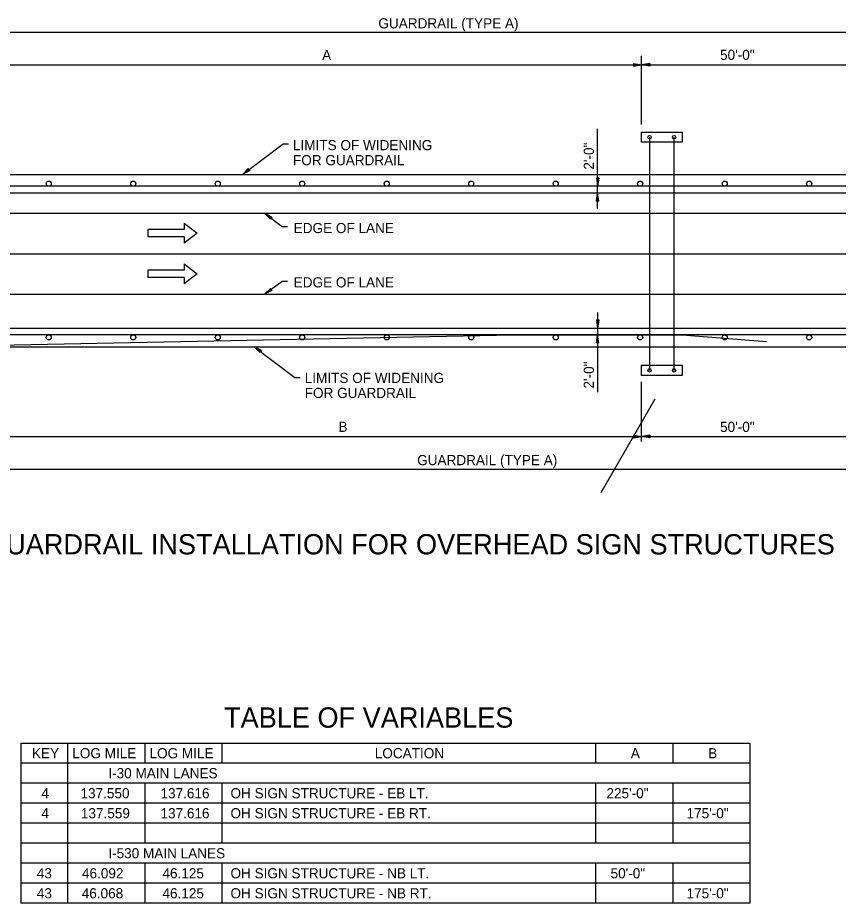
# Model space of a CAD drawing. Extents: x 1373853 to 1374003, y 380191 to 380927.
# Drawn here: x 1373903.9 to 1373952.4, y 380851.9 to 380904.4 of the extents above; entities that cross this region are included whole.
import ezdxf

# ---------------------------------------------------------------- set-up
doc = ezdxf.new("R2010")
doc.units = 0
for name, color, linetype in [('2', 7, 'Continuous'), ('44', 7, 'Continuous'), ('7', 7, 'Continuous'), ('8', 7, 'Continuous'), ('Default', 7, 'Continuous'), ('E_Existing ROW', 7, 'Continuous'), ('Plan Notes', 7, 'Continuous'), ('R_Proposed Road', 7, 'Continuous'), ('R_SIGN_OH', 7, 'Continuous')]:
    doc.layers.add(name, color=color, linetype=linetype)

msp = doc.modelspace()

# ---------------------------------------------------------------- linework, layer by layer
at = {"layer": '2'}
for p, q in [((1373888.075, 380903.499), (1373962.85, 380903.499)), ((1373940.776, 380898.049), (1373940.776, 380902.098)), ((1373903.184, 380901.577), (1373965.149, 380901.575)), ((1373940.776, 380898.049), (1373940.776, 380898.903)), ((1373938.173, 380893.067), (1373938.173, 380897.788)), ((1373917.158, 380895.091), (1373919.557, 380896.904)), ((1373919.557, 380896.904), (1373919.876, 380896.904)), ((1373918.466, 380892.791), (1373919.498, 380892.01)), ((1373919.498, 380892.01), (1373919.818, 380892.01)), ((1373918.466, 380887.991), (1373919.498, 380888.771)), ((1373919.498, 380888.771), (1373919.818, 380888.771)), ((1373938.173, 380886.914), (1373938.173, 380882.193)), ((1373917.854, 380884.891), (1373920.253, 380883.077)), ((1373920.253, 380883.077), (1373920.572, 380883.077)), ((1373940.776, 380879.283), (1373940.776, 380882.812)), ((1373903.176, 380879.572), (1373967.577, 380879.572)), ((1373888.057, 380877.648), (1373962.85, 380877.648))]:
    msp.add_line(p, q, dxfattribs=at)
at = {"layer": '44'}
for p, q in [((1373877.32, 380893.991), (1373970.938, 380893.991)), ((1373877.32, 380885.991), (1373970.938, 380885.991))]:
    msp.add_line(p, q, dxfattribs=at)
at = {"layer": '7'}
for p, q in [((1373940.296, 380901.649), (1373940.776, 380901.575)), ((1373940.296, 380901.649), (1373940.296, 380901.503)), ((1373940.296, 380901.634), (1373940.694, 380901.575)), ((1373940.296, 380901.622), (1373940.613, 380901.575)), ((1373940.296, 380901.61), (1373940.532, 380901.575)), ((1373940.296, 380901.599), (1373940.453, 380901.575)), ((1373940.296, 380901.587), (1373940.372, 380901.575)), ((1373940.296, 380901.503), (1373940.776, 380901.575)), ((1373940.296, 380901.553), (1373940.453, 380901.575)), ((1373940.296, 380901.529), (1373940.613, 380901.575)), ((1373940.296, 380901.515), (1373940.694, 380901.575)), ((1373940.296, 380901.539), (1373940.532, 380901.575)), ((1373940.296, 380901.565), (1373940.372, 380901.575)), ((1373941.256, 380901.649), (1373940.776, 380901.575)), ((1373941.256, 380901.503), (1373940.776, 380901.575)), ((1373941.256, 380901.634), (1373940.857, 380901.575)), ((1373941.256, 380901.515), (1373940.857, 380901.575)), ((1373941.256, 380901.622), (1373940.938, 380901.575)), ((1373941.256, 380901.529), (1373940.938, 380901.575)), ((1373941.256, 380901.61), (1373941.019, 380901.575)), ((1373941.256, 380901.539), (1373941.019, 380901.575)), ((1373941.256, 380901.599), (1373941.098, 380901.575)), ((1373941.256, 380901.553), (1373941.098, 380901.575)), ((1373941.256, 380901.587), (1373941.179, 380901.575)), ((1373941.256, 380901.565), (1373941.179, 380901.575)), ((1373941.256, 380901.649), (1373941.256, 380901.503)), ((1373917.498, 380895.435), (1373917.158, 380895.091)), ((1373917.585, 380895.322), (1373917.158, 380895.091)), ((1373917.507, 380895.427), (1373917.223, 380895.137)), ((1373917.578, 380895.33), (1373917.223, 380895.137)), ((1373917.516, 380895.415), (1373917.29, 380895.188)), ((1373917.569, 380895.34), (1373917.29, 380895.188)), ((1373917.521, 380895.405), (1373917.353, 380895.235)), ((1373917.563, 380895.35), (1373917.353, 380895.235)), ((1373917.527, 380895.397), (1373917.416, 380895.284)), ((1373917.554, 380895.36), (1373917.416, 380895.284)), ((1373917.534, 380895.387), (1373917.483, 380895.333)), ((1373917.55, 380895.372), (1373917.483, 380895.333)), ((1373917.585, 380895.322), (1373917.498, 380895.435)), ((1373938.102, 380894.871), (1373938.173, 380894.391)), ((1373938.245, 380894.871), (1373938.102, 380894.871)), ((1373938.114, 380894.871), (1373938.173, 380894.472)), ((1373938.126, 380894.871), (1373938.173, 380894.553)), ((1373938.138, 380894.871), (1373938.173, 380894.634)), ((1373938.15, 380894.871), (1373938.173, 380894.715)), ((1373938.161, 380894.871), (1373938.173, 380894.794)), ((1373938.245, 380894.871), (1373938.173, 380894.391)), ((1373938.197, 380894.871), (1373938.173, 380894.715)), ((1373938.221, 380894.871), (1373938.173, 380894.553)), ((1373938.233, 380894.871), (1373938.173, 380894.472)), ((1373938.209, 380894.871), (1373938.173, 380894.634)), ((1373938.185, 380894.871), (1373938.173, 380894.794)), ((1373938.099, 380893.511), (1373938.173, 380893.991)), ((1373938.245, 380893.511), (1373938.173, 380893.991)), ((1373938.099, 380893.511), (1373938.245, 380893.511)), ((1373938.114, 380893.511), (1373938.173, 380893.909)), ((1373938.126, 380893.511), (1373938.173, 380893.828)), ((1373938.138, 380893.511), (1373938.173, 380893.747)), ((1373938.15, 380893.511), (1373938.173, 380893.668)), ((1373938.161, 380893.511), (1373938.173, 380893.587)), ((1373938.233, 380893.511), (1373938.173, 380893.909)), ((1373938.219, 380893.511), (1373938.173, 380893.828)), ((1373938.209, 380893.511), (1373938.173, 380893.747)), ((1373938.195, 380893.511), (1373938.173, 380893.668)), ((1373938.183, 380893.511), (1373938.173, 380893.587)), ((1373918.893, 380892.559), (1373918.466, 380892.791)), ((1373918.806, 380892.446), (1373918.466, 380892.791)), ((1373918.886, 380892.552), (1373918.531, 380892.744)), ((1373918.815, 380892.454), (1373918.531, 380892.744)), ((1373918.824, 380892.467), (1373918.598, 380892.693)), ((1373918.877, 380892.541), (1373918.598, 380892.693)), ((1373918.871, 380892.532), (1373918.661, 380892.646)), ((1373918.828, 380892.476), (1373918.661, 380892.646)), ((1373918.835, 380892.484), (1373918.723, 380892.597)), ((1373918.862, 380892.521), (1373918.723, 380892.597)), ((1373918.842, 380892.494), (1373918.791, 380892.548)), ((1373918.858, 380892.509), (1373918.791, 380892.548)), ((1373918.893, 380892.559), (1373918.806, 380892.446)), ((1373918.806, 380888.335), (1373918.466, 380887.991)), ((1373918.893, 380888.222), (1373918.466, 380887.991)), ((1373918.815, 380888.327), (1373918.531, 380888.037)), ((1373918.886, 380888.23), (1373918.531, 380888.037)), ((1373918.824, 380888.315), (1373918.598, 380888.088)), ((1373918.877, 380888.24), (1373918.598, 380888.088)), ((1373918.828, 380888.305), (1373918.661, 380888.135)), ((1373918.871, 380888.25), (1373918.661, 380888.135)), ((1373918.835, 380888.297), (1373918.723, 380888.184)), ((1373918.862, 380888.26), (1373918.723, 380888.184)), ((1373918.842, 380888.287), (1373918.791, 380888.233)), ((1373918.858, 380888.272), (1373918.791, 380888.233)), ((1373918.893, 380888.222), (1373918.806, 380888.335)), ((1373938.099, 380886.471), (1373938.173, 380885.991)), ((1373938.099, 380886.471), (1373938.245, 380886.471)), ((1373938.114, 380886.471), (1373938.173, 380886.072)), ((1373938.126, 380886.471), (1373938.173, 380886.153)), ((1373938.138, 380886.471), (1373938.173, 380886.234)), ((1373938.15, 380886.471), (1373938.173, 380886.313)), ((1373938.161, 380886.471), (1373938.173, 380886.394)), ((1373938.245, 380886.471), (1373938.173, 380885.991)), ((1373938.195, 380886.471), (1373938.173, 380886.313)), ((1373938.219, 380886.471), (1373938.173, 380886.153)), ((1373938.233, 380886.471), (1373938.173, 380886.072)), ((1373938.209, 380886.471), (1373938.173, 380886.234)), ((1373938.183, 380886.471), (1373938.173, 380886.394)), ((1373938.102, 380885.111), (1373938.173, 380885.591)), ((1373938.245, 380885.111), (1373938.173, 380885.591)), ((1373938.245, 380885.111), (1373938.102, 380885.111)), ((1373938.114, 380885.111), (1373938.173, 380885.509)), ((1373938.126, 380885.111), (1373938.173, 380885.428)), ((1373938.138, 380885.111), (1373938.173, 380885.347)), ((1373938.15, 380885.111), (1373938.173, 380885.266)), ((1373938.161, 380885.111), (1373938.173, 380885.187)), ((1373938.233, 380885.111), (1373938.173, 380885.509)), ((1373938.221, 380885.111), (1373938.173, 380885.428)), ((1373938.209, 380885.111), (1373938.173, 380885.347)), ((1373938.197, 380885.111), (1373938.173, 380885.266)), ((1373938.185, 380885.111), (1373938.173, 380885.187)), ((1373918.281, 380884.659), (1373917.854, 380884.891)), ((1373918.194, 380884.547), (1373917.854, 380884.891)), ((1373918.274, 380884.652), (1373917.919, 380884.844)), ((1373918.203, 380884.554), (1373917.919, 380884.844)), ((1373918.212, 380884.567), (1373917.986, 380884.793)), ((1373918.265, 380884.641), (1373917.986, 380884.793)), ((1373918.259, 380884.632), (1373918.049, 380884.746)), ((1373918.216, 380884.576), (1373918.049, 380884.746)), ((1373918.223, 380884.584), (1373918.111, 380884.697)), ((1373918.25, 380884.621), (1373918.111, 380884.697)), ((1373918.23, 380884.594), (1373918.179, 380884.648)), ((1373918.246, 380884.609), (1373918.179, 380884.648)), ((1373918.281, 380884.659), (1373918.194, 380884.547)), ((1373940.296, 380879.646), (1373940.776, 380879.572)), ((1373940.296, 380879.646), (1373940.296, 380879.5)), ((1373940.296, 380879.632), (1373940.694, 380879.572)), ((1373940.296, 380879.62), (1373940.613, 380879.572)), ((1373940.296, 380879.608), (1373940.532, 380879.572)), ((1373940.296, 380879.596), (1373940.453, 380879.572)), ((1373940.296, 380879.584), (1373940.372, 380879.572)), ((1373940.296, 380879.5), (1373940.776, 380879.572)), ((1373940.296, 380879.551), (1373940.453, 380879.572)), ((1373940.296, 380879.527), (1373940.613, 380879.572)), ((1373940.296, 380879.512), (1373940.694, 380879.572)), ((1373940.296, 380879.536), (1373940.532, 380879.572)), ((1373940.296, 380879.562), (1373940.372, 380879.572)), ((1373941.256, 380879.646), (1373940.776, 380879.572)), ((1373941.256, 380879.5), (1373940.776, 380879.572)), ((1373941.256, 380879.632), (1373940.857, 380879.572)), ((1373941.256, 380879.512), (1373940.857, 380879.572)), ((1373941.256, 380879.62), (1373940.938, 380879.572)), ((1373941.256, 380879.527), (1373940.938, 380879.572)), ((1373941.256, 380879.608), (1373941.019, 380879.572)), ((1373941.256, 380879.536), (1373941.019, 380879.572)), ((1373941.256, 380879.596), (1373941.098, 380879.572)), ((1373941.256, 380879.551), (1373941.098, 380879.572)), ((1373941.256, 380879.584), (1373941.179, 380879.572)), ((1373941.256, 380879.562), (1373941.179, 380879.572)), ((1373941.256, 380879.646), (1373941.256, 380879.5))]:
    msp.add_line(p, q, dxfattribs=at)
at = {"layer": 'Default'}
for p, q in [((1373913.712, 380892.196), (1373913.712, 380891.829)), ((1373913.712, 380892.196), (1373914.475, 380891.608)), ((1373913.712, 380891.829), (1373911.551, 380891.829)), ((1373911.551, 380891.829), (1373911.551, 380891.388)), ((1373913.712, 380891.388), (1373911.551, 380891.388)), ((1373914.475, 380891.608), (1373913.712, 380891.021)), ((1373913.712, 380891.388), (1373913.712, 380891.021)), ((1373913.712, 380889.796), (1373913.712, 380889.429)), ((1373913.712, 380889.796), (1373914.475, 380889.208)), ((1373913.712, 380889.429), (1373911.551, 380889.429)), ((1373911.551, 380889.429), (1373911.551, 380888.988)), ((1373913.712, 380888.988), (1373911.551, 380888.988)), ((1373914.475, 380889.208), (1373913.712, 380888.621)), ((1373913.712, 380888.988), (1373913.712, 380888.621))]:
    msp.add_line(p, q, dxfattribs=at)
at = {"layer": 'E_Existing ROW'}
msp.add_lwpolyline([(1373938.379, 380876.269), (1373941.576, 380881.805)], dxfattribs=at)
msp.add_lwpolyline([(1373938.379, 380876.269), (1373941.576, 380881.805)], dxfattribs=at)
at = {"layer": 'Plan Notes'}
for p, q in [((1373904.047, 380861.425), (1373947.188, 380861.425)), ((1373904.047, 380861.425), (1373904.047, 380851.948)), ((1373906.804, 380861.425), (1373906.804, 380851.948)), ((1373911.374, 380861.425), (1373911.374, 380860.24)), ((1373915.943, 380861.425), (1373915.943, 380860.24)), ((1373938.048, 380861.425), (1373938.048, 380860.24)), ((1373942.618, 380861.425), (1373942.618, 380860.24)), ((1373947.188, 380861.425), (1373947.188, 380851.948)), ((1373911.374, 380859.056), (1373911.374, 380855.502)), ((1373915.943, 380859.056), (1373915.943, 380855.502)), ((1373938.048, 380859.056), (1373938.048, 380855.502)), ((1373942.618, 380859.056), (1373942.618, 380855.502)), ((1373911.374, 380854.317), (1373911.374, 380851.948)), ((1373915.943, 380854.317), (1373915.943, 380851.948)), ((1373938.048, 380854.317), (1373938.048, 380851.948)), ((1373942.618, 380854.317), (1373942.618, 380851.948))]:
    msp.add_line(p, q, dxfattribs=at)
for points in [[(1373947.188, 380860.24), (1373904.047, 380860.24)], [(1373947.188, 380859.056), (1373904.047, 380859.056)], [(1373947.188, 380857.871), (1373904.047, 380857.871)], [(1373947.188, 380856.687), (1373904.047, 380856.687)], [(1373947.188, 380855.502), (1373904.047, 380855.502)], [(1373947.188, 380854.317), (1373904.047, 380854.317)], [(1373947.188, 380853.133), (1373904.047, 380853.133)], [(1373947.188, 380851.948), (1373904.047, 380851.948)]]:
    msp.add_lwpolyline(points, dxfattribs=at)
at = {"layer": 'R_Proposed Road'}
for p, q in [((1373877.32, 380892.791), (1373970.938, 380892.791)), ((1373877.32, 380890.391), (1373970.938, 380890.391)), ((1373877.32, 380887.991), (1373970.938, 380887.991)), ((1373893.176, 380884.791), (1373933.176, 380885.591)), ((1373933.176, 380885.591), (1373943.176, 380885.591)), ((1373943.176, 380885.591), (1373948.176, 380885.191))]:
    msp.add_line(p, q, dxfattribs=at)
for points in [[(1373903.196, 380895.091), (1373933.183, 380895.091)], [(1373933.183, 380895.091), (1373960.176, 380895.091)], [(1373958.176, 380894.791), (1373953.176, 380894.391), (1373940.692, 380894.391)], [(1373905.692, 380894.391), (1373903.176, 380894.391)], [(1373908.192, 380894.391), (1373905.692, 380894.391)], [(1373910.692, 380894.391), (1373908.192, 380894.391)], [(1373915.692, 380894.391), (1373910.692, 380894.391)], [(1373918.192, 380894.391), (1373915.692, 380894.391)], [(1373920.692, 380894.391), (1373918.192, 380894.391)], [(1373925.692, 380894.391), (1373920.692, 380894.391)], [(1373928.192, 380894.391), (1373925.692, 380894.391)], [(1373930.692, 380894.391), (1373928.192, 380894.391)], [(1373933.176, 380894.391), (1373930.692, 380894.391)], [(1373935.692, 380894.391), (1373933.176, 380894.391)], [(1373938.192, 380894.391), (1373935.692, 380894.391)], [(1373940.692, 380894.391), (1373938.192, 380894.391)], [(1373905.692, 380885.591), (1373903.176, 380885.591)], [(1373908.192, 380885.591), (1373905.692, 380885.591)], [(1373910.692, 380885.591), (1373908.192, 380885.591)], [(1373915.692, 380885.591), (1373910.692, 380885.591)], [(1373918.192, 380885.591), (1373915.692, 380885.591)], [(1373920.692, 380885.591), (1373918.192, 380885.591)], [(1373925.692, 380885.591), (1373920.692, 380885.591)], [(1373928.192, 380885.591), (1373925.692, 380885.591)], [(1373930.692, 380885.591), (1373928.192, 380885.591)], [(1373933.176, 380885.591), (1373930.692, 380885.591)], [(1373935.692, 380885.591), (1373933.176, 380885.591)], [(1373938.192, 380885.591), (1373935.692, 380885.591)], [(1373940.692, 380885.591), (1373938.192, 380885.591)], [(1373958.176, 380885.191), (1373953.176, 380885.591), (1373940.692, 380885.591)], [(1373903.196, 380884.891), (1373933.183, 380884.891)], [(1373933.183, 380884.891), (1373960.176, 380884.891)]]:
    msp.add_lwpolyline(points, dxfattribs=at)
for centre in [(1373905.692, 380894.54), (1373910.692, 380894.54), (1373915.692, 380894.54), (1373920.692, 380894.54), (1373925.692, 380894.54), (1373930.692, 380894.54), (1373935.692, 380894.54), (1373940.692, 380894.54), (1373945.692, 380894.54), (1373950.692, 380894.54), (1373905.692, 380885.441), (1373910.692, 380885.441), (1373915.692, 380885.441), (1373920.692, 380885.441), (1373925.692, 380885.441), (1373930.692, 380885.441), (1373935.692, 380885.441), (1373940.692, 380885.441), (1373945.692, 380885.441), (1373950.692, 380885.441)]:
    msp.add_circle(centre, 0.15, dxfattribs=at)
at = {"layer": 'R_SIGN_OH'}
for p, q in [((1373940.776, 380897.591), (1373943.176, 380897.591)), ((1373940.776, 380896.991), (1373940.776, 380897.591)), ((1373941.251, 380897.291), (1373941.251, 380890.391)), ((1373942.701, 380890.391), (1373942.701, 380897.291)), ((1373943.176, 380897.591), (1373943.176, 380896.991)), ((1373943.176, 380896.991), (1373940.776, 380896.991)), ((1373941.251, 380890.391), (1373941.251, 380883.491)), ((1373942.701, 380883.491), (1373942.701, 380890.391)), ((1373940.776, 380883.791), (1373943.176, 380883.791)), ((1373940.776, 380883.191), (1373940.776, 380883.791)), ((1373943.176, 380883.791), (1373943.176, 380883.191)), ((1373943.176, 380883.191), (1373940.776, 380883.191))]:
    msp.add_line(p, q, dxfattribs=at)
for centre in [(1373941.251, 380897.291), (1373942.701, 380897.291), (1373941.251, 380883.491), (1373942.701, 380883.491)]:
    msp.add_circle(centre, 0.1, dxfattribs=at)

# ---------------------------------------------------------------- texts
at = {"layer": '2'}
for s, rotation, p in [('GUARDRAIL (TYPE A)', 0, (1373925.199, 380903.73)), ('A', 0, (1373921.872, 380901.853)), ('50\'-0"', 0, (1373945.419, 380901.864)), ('LIMITS OF WIDENING', 0, (1373920.144, 380896.522)), ('2\'-0"', 90, (1373937.952, 380895.37)), ('FOR GUARDRAIL', 0, (1373920.144, 380895.632)), ('EDGE OF LANE', 0, (1373920.187, 380891.614)), ('EDGE OF LANE', 0, (1373920.187, 380888.4)), ('2\'-0"', 90, (1373937.952, 380882.414)), ('LIMITS OF WIDENING', 0, (1373920.84, 380882.744)), ('FOR GUARDRAIL', 0, (1373920.84, 380881.854)), ('B', 0, (1373922.836, 380879.85)), ('50\'-0"', 0, (1373945.419, 380879.844)), ('GUARDRAIL (TYPE A)', 0, (1373927.494, 380877.879)), ('KEY', 0, (1373904.698, 380860.532)), ('LOG MILE', 0, (1373907.085, 380860.532)), ('LOG MILE', 0, (1373911.655, 380860.532)), ('LOCATION', 0, (1373924.985, 380860.532)), ('A', 0, (1373940.137, 380860.532)), ('B', 0, (1373944.716, 380860.532)), ('I-30 MAIN LANES', 0, (1373909.217, 380859.348)), ('4', 0, (1373905.255, 380858.163)), ('137.550', 0, (1373907.57, 380858.163)), ('137.616', 0, (1373912.305, 380858.163)), ('OH SIGN STRUCTURE - EB LT.', 0, (1373916.447, 380858.163)), ('225\'-0"', 0, (1373938.696, 380858.163)), ('4', 0, (1373905.255, 380856.979)), ('137.559', 0, (1373907.593, 380856.979)), ('137.616', 0, (1373912.305, 380856.979)), ('OH SIGN STRUCTURE - EB RT.', 0, (1373916.447, 380856.979)), ('175\'-0"', 0, (1373943.436, 380856.979)), ('I-530 MAIN LANES', 0, (1373909.217, 380854.61)), ('43', 0, (1373904.986, 380853.425)), ('46.092', 0, (1373907.657, 380853.425)), ('46.125', 0, (1373912.421, 380853.425)), ('OH SIGN STRUCTURE - NB LT.', 0, (1373916.447, 380853.425)), ('50\'-0"', 0, (1373938.941, 380853.425)), ('43', 0, (1373904.986, 380852.241)), ('46.068', 0, (1373907.643, 380852.241)), ('46.125', 0, (1373912.421, 380852.241)), ('OH SIGN STRUCTURE - NB RT.', 0, (1373916.447, 380852.241)), ('175\'-0"', 0, (1373943.436, 380852.241))]:
    msp.add_text(s, height=0.6, rotation=rotation, dxfattribs=at).set_placement(p)
at = {"layer": '8'}
for s, p in [('PARALLEL GUARDRAIL INSTALLATION FOR OVERHEAD SIGN STRUCTURES', (1373893.359, 380872.597)), ('TABLE OF VARIABLES', (1373916.065, 380862.342))]:
    msp.add_text(s, height=1.2, rotation=0, dxfattribs=at).set_placement(p)

doc.saveas('drawing.dxf')
